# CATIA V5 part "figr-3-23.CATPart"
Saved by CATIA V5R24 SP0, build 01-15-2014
Part number: figr-3-23
Bounding box of the stored display mesh (mm): x 0 to 0, y -2187335.75 to 2141537, z -681609 to 2530522.25
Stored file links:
  D:\KAVITA\CATIA V5-6R2014 Project_ Kavita\CATIA V5-6R2014_partfiles\Partfiles\c03_catia_v5-6r2014_prt\figr-3-23.CATPart
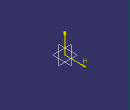
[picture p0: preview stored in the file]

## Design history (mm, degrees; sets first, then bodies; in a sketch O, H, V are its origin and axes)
Body1 (main body)
  Sketch1 on yz-plane, origin (0, 0, 0), H (0, 1, 0), V (0, 0, 1)
    line L1 through (-830059.7691, 1160197.0782) direction (0.7237, 0.6901)
    line L2 through (299240.8462, 476164.2676) direction (0.8467, -0.5321)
